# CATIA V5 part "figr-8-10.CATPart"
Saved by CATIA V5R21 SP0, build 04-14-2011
Part number: Part2
Bounding box of the stored display mesh (mm): x -37.886 to 37.886, y -61.415 to 61.415, z 29 to 58
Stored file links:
  D:\CATIA V5R21 E-RESOURCES\CATIA-V5R21\catia-v5r21-prt\c08-catia-v5r20-prt\c08-catia-v5r21-figr-8-10.CATPart
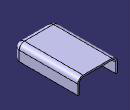
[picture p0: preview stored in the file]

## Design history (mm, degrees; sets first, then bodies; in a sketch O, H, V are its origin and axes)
Body1 (main body)
  Sketch1 on xy-plane, origin (0, 0, 0), H (1, 0, 0), V (0, 1, 0)
    line L1 (37.8862, 61.4155) -> (37.8862, -61.4155)
    line L2 (37.8862, -61.4155) -> (-37.8862, -61.4155)
    line L3 (-37.8862, -61.4155) -> (-37.8862, 61.4155)
    line L4 (-37.8862, 61.4155) -> (37.8862, 61.4155)
    vertical: L1 V, L3 V
    horizontal: L2 H, L4 H
    equidistance: L1 L3 O, L2 L4 O
  Pad1: profile Sketch1, direction (0, 0, 1), length 29
  Fillet1: radius 10, on edge [face of Pad1 | face of Pad1] (x5)
  Shell1: ExtOffset 0, Face (face of Pad1; face of Pad1), IntOffset 3
  Symmetry1: ToTransfor Shell1, Reference face of Pad1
